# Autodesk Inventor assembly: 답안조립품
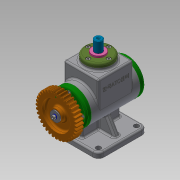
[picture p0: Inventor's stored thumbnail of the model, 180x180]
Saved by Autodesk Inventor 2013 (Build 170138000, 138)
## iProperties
Created: 2019-01
Part Number: 답안조립품
Document SubType Name: Assembly
Designer: Administrator
Mass: 1743.43 g
Surface Area: 1517.22 cm^2
Volume: 492 cm^3
Density: 3.54356 g/cm^3
Author: Administrator
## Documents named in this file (18)
- C:\Users\Administrator\Desktop\390107V1019\답안조립품.iam
- C:\Users\Administrator\Desktop\390107V1019\본체.ipt
- C:\Users\Administrator\Desktop\390107V1019\뒤커버.ipt
- C:\Users\Administrator\Desktop\390107V1019\멈춤링.ipt
- C:\Users\Administrator\Desktop\390107V1019\베어링 6203.ipt
- C:\Users\Administrator\Desktop\390107V1019\볼트 M4.ipt
- C:\Users\Administrator\Desktop\390107V1019\부시.ipt
- C:\Users\Administrator\Desktop\390107V1019\상부커버.ipt
- C:\Users\Administrator\Desktop\390107V1019\스퍼기어.ipt
- C:\Users\Administrator\Desktop\390107V1019\스프링와셔.ipt
- C:\Users\Administrator\Desktop\390107V1019\스프링조립용 와셔.ipt
- C:\Users\Administrator\Desktop\390107V1019\슬라이더.ipt
- C:\Users\Administrator\Desktop\390107V1019\앞커버.ipt
- C:\Users\Administrator\Desktop\390107V1019\오일 실 17 30 5.ipt
- C:\Users\Administrator\Desktop\390107V1019\키 4x4x12.ipt
- C:\Users\Administrator\Desktop\390107V1019\편심축.ipt
- C:\Users\Administrator\Desktop\390107V1019\평와셔.ipt
- C:\Users\Administrator\Desktop\390107V1019\가변스프링1.ipt
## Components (1 placed, 1 different names)
1. 가변스프링1:1
